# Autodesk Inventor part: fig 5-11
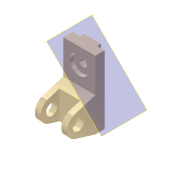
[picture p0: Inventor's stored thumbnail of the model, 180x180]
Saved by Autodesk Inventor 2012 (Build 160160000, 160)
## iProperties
Shininess: 65.0
Angle Display Precision: 2
Document Length Units: 11269
Document Angle Units: 11279
Document Time Units: 11290
Document Mass Units: 11283
Document Length Units Precision: 3
Document Angle Units Precision: 2
Compacted: False
Created: 2001-11
Part Number: fig 5-11
Document SubType Name: Modeling
Designer: Renu Muthoo
Density: 1 g/cm^3
Material: Default
Density: 0.0
Volumn: 0.0
Area: 0.0
PropertySet Name: Model Information
Control State: 0
Master: False
Checked Out: False
Author: Renu Muthoo
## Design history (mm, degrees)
node "Sketch1"
sketch "Sketch2"
  geometry: L1 (33.257, 104.664)-(33.257, -75.336); L2 (33.257, -75.336)-(8.257, -75.336); L3 (8.257, -75.336)-(-45.451, -59.045); L4 (-45.451, -1.628)-(8.257, 14.664); L5 (8.257, 14.664)-(8.257, 104.664); L6 (8.257, 104.664)-(33.257, 104.664); C1 r 15 at (-36.743, -30.336); A1 r 30 centre (-36.743, -30.336) between (-45.451, -1.628) and (-45.451, -59.045)
  constraints: 12 end point, 2 centre point, 2 equal length, 2 parallel, 2 point on circle, 2 tangent, 1 coincident, 1 perpendicular, 1 vertical
  dimensions: "d0" = 180 distance of L1.start L1.end; "d1" = 30 radius of A1; "d2" = 25 distance of L5.end L1.start; "d3" = 45 distance from line of L2 A1.centre; "d4" = 70 distance from line of L1 A1.centre; "d5" = 30 diameter of C1
extrude "Extrusion1" new body sketch "Sketch2" distance "d6" = 85; taper "d7" = 0 deg
workplane "Work Plane1"
sketch "Sketch3"
  geometry: L1 (15, 62.364)-(70, 62.364); L2 (70, 62.364)-(70, -52.386); L3 (70, -52.386)-(15, -52.386); L4 (15, -52.386)-(15, 62.364); L5 (0, -45)-(0, -28.708) reference
  constraints: 8 end point, 2 parallel, 1 horizontal, 1 perpendicular
  dimensions: "d8" = 55 distance of L1.start L1.end; "d9" = 15 distance between parallel lines of L5 L4
extrude "Extrusion2" cut sketch "Sketch3" distance "d10" = 50; taper "d11" = 0 deg
sketch "Sketch4"
  geometry: L1 (0, 25)-(85, 25) reference; L2 (0, 0)-(0, 25) reference; L3 (20, 25)-(65, 25); L4 (65, 25)-(65, 35); L5 (65, 35)-(20, 35); L6 (20, 35)-(20, 25)
  constraints: 8 end point, 2 parallel, 1 horizontal, 1 perpendicular, 1 point on line
  dimensions: "d12" = 45 distance of L4.end L5.end; "d13" = 10 distance of L3.end L4.end; "d14" = 20 distance between parallel lines of L2 L6
extrude "Extrusion3" join sketch "Sketch4" stored distance "d15" = 50; taper "d16" = 0 deg
sketch "Sketch5"
  geometry: L1 (85, 0)-(85, 90) reference; L2 (0, 90)-(85, 90) reference; 1 further point
  dimensions: "d17" = 42 distance from line of L2 point (42.5, 48); "d18" = 42.5 distance from line of L1 point (42.5, 48)
hole "Hole1" sketch "Sketch5" at (42.5, 48) diameter "d19" = 20; stored, may be unused: countersink angle "d23" = 82 deg, drill point angle "d25" = 118 deg; dims "d20" = 6, "d21" = 50, "d22" = 10, "d24" = 8
workplane "Work Plane8"
body "Solid1"
other parameters: "d28" = 135 deg
